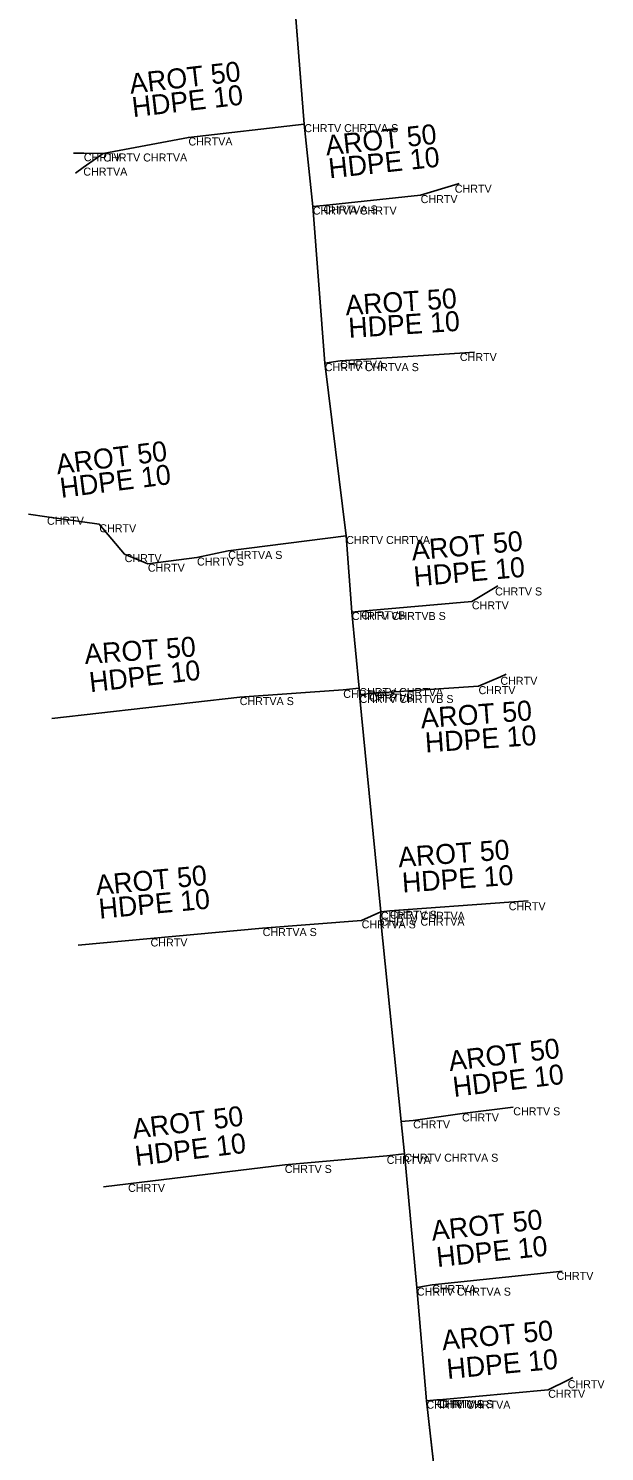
# Model space of a CAD drawing. Extents: x -651943 to -618711, y -1138561 to -1100552.
# Drawn here: x -641106.3 to -641084.8, y -1114595.2 to -1114541.8 of the extents above; entities that cross this region are included whole.
import ezdxf

# ---------------------------------------------------------------- set-up
doc = ezdxf.new("R2010")
doc.units = 0
for name, color, linetype in [('KT optika', 7, 'Continuous'), ('KT trasa', 7, 'Continuous'), ('KT zařízení', 7, 'Continuous')]:
    doc.layers.add(name, color=color, linetype=linetype)

msp = doc.modelspace()

# ---------------------------------------------------------------- linework, layer by layer
at = {"layer": 'KT optika'}
for p, q in [((-641096.85, -1114534.63), (-641096, -1114545.43)), ((-641100.34, -1114545.93), (-641103.53, -1114546.53)), ((-641096, -1114545.43), (-641100.34, -1114545.93)), ((-641096, -1114545.43), (-641095.68, -1114548.52)), ((-641095.68, -1114548.52), (-641095.28, -1114548.48)), ((-641095.68, -1114548.52), (-641095.23, -1114554.39)), ((-641095.28, -1114548.48), (-641091.64, -1114548.09)), ((-641095.23, -1114554.39), (-641094.66, -1114554.3)), ((-641095.23, -1114554.39), (-641094.43, -1114560.87)), ((-641102.73, -1114561.55), (-641103.68, -1114560.43)), ((-641094.43, -1114560.87), (-641098.85, -1114561.43)), ((-641094.43, -1114560.87), (-641094.22, -1114563.72)), ((-641101.86, -1114561.91), (-641102.73, -1114561.55)), ((-641100.02, -1114561.68), (-641101.86, -1114561.91)), ((-641098.85, -1114561.43), (-641100.02, -1114561.68)), ((-641093.86, -1114563.69), (-641089.72, -1114563.32)), ((-641094.22, -1114563.72), (-641093.86, -1114563.69)), ((-641094.22, -1114563.72), (-641093.94, -1114566.57)), ((-641094.54, -1114566.64), (-641098.42, -1114566.91)), ((-641093.94, -1114566.57), (-641094.54, -1114566.64)), ((-641093.93, -1114566.83), (-641093.94, -1114566.57)), ((-641105.453, -1114567.71), (-641098.42, -1114566.91)), ((-641093.13, -1114574.96), (-641093.93, -1114566.83)), ((-641093.85, -1114575.28), (-641097.56, -1114575.57)), ((-641093.13, -1114574.96), (-641093.85, -1114575.28)), ((-641093.13, -1114574.96), (-641093.14, -1114575.18)), ((-641092.79, -1114574.92), (-641093.13, -1114574.96)), ((-641091.92, -1114582.78), (-641090.09, -1114582.52)), ((-641090.09, -1114582.52), (-641088.17, -1114582.29)), ((-641092.371, -1114582.825), (-641091.92, -1114582.78)), ((-641092.91, -1114584.11), (-641096.73, -1114584.45)), ((-641092.25, -1114584.03), (-641092.91, -1114584.11)), ((-641092.25, -1114584.03), (-641091.78, -1114589.05)), ((-641091.78, -1114589.05), (-641091.21, -1114588.95)), ((-641091.78, -1114589.05), (-641091.42, -1114593.29)), ((-641090.95, -1114593.26), (-641086.86, -1114592.88)), ((-641091.42, -1114593.29), (-641090.33, -1114602.87))]:
    msp.add_line(p, q, dxfattribs=at)
for points in [[(-641103.53, -1114546.53), (-641104.26, -1114546.52), (-641104.649, -1114546.515)], [(-641103.53, -1114546.53), (-641104.28, -1114547.06), (-641104.573, -1114547.267)], [(-641091.64, -1114548.09), (-641090.36, -1114547.7), (-641090.194, -1114547.649)], [(-641094.66, -1114554.3), (-641090.17, -1114554.01), (-641089.623, -1114553.975)], [(-641103.68, -1114560.43), (-641105.64, -1114560.15), (-641106.334, -1114560.051)], [(-641089.72, -1114563.32), (-641088.85, -1114562.8), (-641088.748, -1114562.739)], [(-641088.431, -1114566.056), (-641088.65, -1114566.15), (-641089.47, -1114566.5)], [(-641089.47, -1114566.5), (-641093.56, -1114566.78), (-641093.93, -1114566.83)], [(-641087.614, -1114574.548), (-641088.34, -1114574.6), (-641092.79, -1114574.92)], [(-641093.14, -1114575.18), (-641092.371, -1114582.825), (-641092.25, -1114584.03)], [(-641097.56, -1114575.57), (-641101.76, -1114575.96), (-641104.477, -1114576.212)], [(-641096.73, -1114584.45), (-641102.6, -1114585.16), (-641103.517, -1114585.271)], [(-641091.21, -1114588.95), (-641086.55, -1114588.46), (-641086.337, -1114588.438)], [(-641086.86, -1114592.88), (-641086.13, -1114592.52), (-641085.934, -1114592.423)], [(-641091.42, -1114593.29), (-641091.03, -1114593.26), (-641090.95, -1114593.26)]]:
    msp.add_lwpolyline(points, dxfattribs=at)
at = {"layer": 'KT trasa'}
for p, q in [((-641096.85, -1114534.63), (-641096, -1114545.43)), ((-641100.34, -1114545.93), (-641103.53, -1114546.53)), ((-641096, -1114545.43), (-641100.34, -1114545.93)), ((-641096, -1114545.43), (-641095.68, -1114548.52)), ((-641095.68, -1114548.52), (-641095.28, -1114548.48)), ((-641095.68, -1114548.52), (-641095.23, -1114554.39)), ((-641095.28, -1114548.48), (-641091.64, -1114548.09)), ((-641095.23, -1114554.39), (-641094.66, -1114554.3)), ((-641095.23, -1114554.39), (-641094.43, -1114560.87)), ((-641102.73, -1114561.55), (-641103.68, -1114560.43)), ((-641094.43, -1114560.87), (-641098.85, -1114561.43)), ((-641094.43, -1114560.87), (-641094.22, -1114563.72)), ((-641101.86, -1114561.91), (-641102.73, -1114561.55)), ((-641100.02, -1114561.68), (-641101.86, -1114561.91)), ((-641098.85, -1114561.43), (-641100.02, -1114561.68)), ((-641093.86, -1114563.69), (-641089.72, -1114563.32)), ((-641094.22, -1114563.72), (-641093.86, -1114563.69)), ((-641094.22, -1114563.72), (-641093.94, -1114566.57)), ((-641094.54, -1114566.64), (-641098.42, -1114566.91)), ((-641093.94, -1114566.57), (-641094.54, -1114566.64)), ((-641093.93, -1114566.83), (-641093.94, -1114566.57)), ((-641105.453, -1114567.71), (-641098.42, -1114566.91)), ((-641093.13, -1114574.96), (-641093.93, -1114566.83)), ((-641093.85, -1114575.28), (-641097.56, -1114575.57)), ((-641093.13, -1114574.96), (-641093.85, -1114575.28)), ((-641093.13, -1114574.96), (-641093.14, -1114575.18)), ((-641092.79, -1114574.92), (-641093.13, -1114574.96)), ((-641091.92, -1114582.78), (-641090.09, -1114582.52)), ((-641090.09, -1114582.52), (-641088.17, -1114582.29)), ((-641092.371, -1114582.825), (-641091.92, -1114582.78)), ((-641092.91, -1114584.11), (-641096.73, -1114584.45)), ((-641092.25, -1114584.03), (-641092.91, -1114584.11)), ((-641092.25, -1114584.03), (-641091.78, -1114589.05)), ((-641091.78, -1114589.05), (-641091.21, -1114588.95)), ((-641091.78, -1114589.05), (-641091.42, -1114593.29)), ((-641090.95, -1114593.26), (-641086.86, -1114592.88)), ((-641091.42, -1114593.29), (-641090.33, -1114602.87))]:
    msp.add_line(p, q, dxfattribs=at)
for points in [[(-641103.53, -1114546.53), (-641104.26, -1114546.52), (-641104.649, -1114546.515)], [(-641103.53, -1114546.53), (-641104.28, -1114547.06), (-641104.573, -1114547.267)], [(-641091.64, -1114548.09), (-641090.36, -1114547.7), (-641090.194, -1114547.649)], [(-641094.66, -1114554.3), (-641090.17, -1114554.01), (-641089.623, -1114553.975)], [(-641103.68, -1114560.43), (-641105.64, -1114560.15), (-641106.334, -1114560.051)], [(-641089.72, -1114563.32), (-641088.85, -1114562.8), (-641088.748, -1114562.739)], [(-641088.431, -1114566.056), (-641088.65, -1114566.15), (-641089.47, -1114566.5)], [(-641089.47, -1114566.5), (-641093.56, -1114566.78), (-641093.93, -1114566.83)], [(-641087.614, -1114574.548), (-641088.34, -1114574.6), (-641092.79, -1114574.92)], [(-641093.14, -1114575.18), (-641092.371, -1114582.825), (-641092.25, -1114584.03)], [(-641097.56, -1114575.57), (-641101.76, -1114575.96), (-641104.477, -1114576.212)], [(-641096.73, -1114584.45), (-641102.6, -1114585.16), (-641103.517, -1114585.271)], [(-641091.21, -1114588.95), (-641086.55, -1114588.46), (-641086.337, -1114588.438)], [(-641086.86, -1114592.88), (-641086.13, -1114592.52), (-641085.934, -1114592.423)], [(-641091.42, -1114593.29), (-641091.03, -1114593.26), (-641090.95, -1114593.26)]]:
    msp.add_lwpolyline(points, dxfattribs=at)
at = {"layer": 'KT zařízení'}
for p, q in [((-641098.42, -1114566.91), (-641105.453, -1114567.71)), ((-641092.91, -1114584.11), (-641096.73, -1114584.45)), ((-641092.25, -1114584.03), (-641092.91, -1114584.11)), ((-641096.73, -1114584.45), (-641102.6, -1114585.16)), ((-641102.6, -1114585.16), (-641103.517, -1114585.271))]:
    msp.add_line(p, q, dxfattribs=at)
for points in [[(-641096.85, -1114534.63), (-641096, -1114545.43), (-641095.68, -1114548.52), (-641095.23, -1114554.39), (-641094.43, -1114560.87), (-641094.22, -1114563.72), (-641093.94, -1114566.57), (-641093.93, -1114566.83), (-641093.13, -1114574.96), (-641093.14, -1114575.18), (-641092.371, -1114582.825), (-641092.25, -1114584.03), (-641091.78, -1114589.05), (-641091.42, -1114593.29), (-641090.33, -1114602.87)], [(-641096, -1114545.43), (-641100.34, -1114545.93), (-641103.53, -1114546.53), (-641104.26, -1114546.52), (-641104.649, -1114546.515)], [(-641104.573, -1114547.267), (-641104.28, -1114547.06), (-641103.53, -1114546.53)], [(-641090.194, -1114547.649), (-641090.36, -1114547.7), (-641091.64, -1114548.09), (-641095.28, -1114548.48)], [(-641089.623, -1114553.975), (-641090.17, -1114554.01), (-641094.66, -1114554.3), (-641095.23, -1114554.39)], [(-641094.43, -1114560.87), (-641098.85, -1114561.43), (-641100.02, -1114561.68), (-641101.86, -1114561.91), (-641102.73, -1114561.55), (-641103.68, -1114560.43), (-641105.64, -1114560.15), (-641106.334, -1114560.051)], [(-641088.748, -1114562.739), (-641088.85, -1114562.8), (-641089.72, -1114563.32), (-641093.86, -1114563.69)], [(-641088.431, -1114566.056), (-641088.65, -1114566.15), (-641089.47, -1114566.5), (-641093.56, -1114566.78)], [(-641093.94, -1114566.57), (-641094.54, -1114566.64), (-641098.42, -1114566.91)], [(-641092.79, -1114574.92), (-641088.34, -1114574.6), (-641087.614, -1114574.548)], [(-641104.477, -1114576.212), (-641101.76, -1114575.96), (-641097.56, -1114575.57), (-641093.85, -1114575.28), (-641093.13, -1114574.96)], [(-641091.92, -1114582.78), (-641090.09, -1114582.52), (-641088.17, -1114582.29)], [(-641086.337, -1114588.438), (-641086.55, -1114588.46), (-641091.21, -1114588.95), (-641091.78, -1114589.05)], [(-641091.03, -1114593.26), (-641090.95, -1114593.26), (-641086.86, -1114592.88), (-641086.13, -1114592.52), (-641085.934, -1114592.423)]]:
    msp.add_lwpolyline(points, dxfattribs=at)

# ---------------------------------------------------------------- texts
for s, rotation, p in [('AROT 50', 6.5719, (-641102.508, -1114544.291)), ('HDPE 10', 6.5719, (-641102.413, -1114545.171)), ('AROT 50', 6.1155, (-641095.168, -1114546.607)), ('HDPE 10', 6.1155, (-641095.053, -1114547.464)), ('AROT 50', 3.6955, (-641094.438, -1114552.595)), ('HDPE 10', 3.6955, (-641094.324, -1114553.446)), ('AROT 50', 7.125, (-641105.253, -1114558.559)), ('HDPE 10', 7.2207, (-641105.108, -1114559.444)), ('AROT 50', 5.1071, (-641091.952, -1114561.79)), ('HDPE 10', 5.1071, (-641091.869, -1114562.767)), ('AROT 50', 3.9807, (-641104.214, -1114565.673)), ('HDPE 10', 6.4895, (-641104.015, -1114566.729)), ('AROT 50', 4.2317, (-641091.615, -1114568.083)), ('HDPE 10', 3.9163, (-641091.452, -1114568.989)), ('AROT 50', 4.1131, (-641092.458, -1114573.291)), ('AROT 50', 5.3051, (-641103.786, -1114574.338)), ('HDPE 10', 4.1131, (-641092.311, -1114574.243)), ('HDPE 10', 5.299, (-641103.668, -1114575.221)), ('AROT 50', 6.831, (-641090.546, -1114580.931)), ('HDPE 10', 6.831, (-641090.39, -1114581.902)), ('AROT 50', 6.8967, (-641102.399, -1114583.473)), ('HDPE 10', 6.8967, (-641102.3, -1114584.492)), ('AROT 50', 6.0026, (-641091.203, -1114587.29)), ('HDPE 10', 6.0026, (-641091.012, -1114588.282)), ('AROT 50', 5.3081, (-641090.813, -1114591.399)), ('HDPE 10', 5.3081, (-641090.632, -1114592.475))]:
    msp.add_text(s, height=0.75, rotation=rotation, dxfattribs=at).set_placement(p)
for s, p in [('CHRTVA', (-641100.34, -1114546.23)), ('CHRTV CHRTVA S', (-641096, -1114545.73)), ('CHRTV', (-641104.26, -1114546.82)), ('CHRTV CHRTVA', (-641103.53, -1114546.83)), ('CHRTVA', (-641104.28, -1114547.36)), ('CHRTV', (-641090.36, -1114548)), ('CHRTVA CHRTV', (-641095.68, -1114548.82)), ('CHRTVA S', (-641095.28, -1114548.78)), ('CHRTV', (-641091.64, -1114548.39)), ('CHRTV CHRTVA S', (-641095.23, -1114554.69)), ('CHRTVA', (-641094.66, -1114554.6)), ('CHRTV', (-641090.17, -1114554.31)), ('CHRTV', (-641105.64, -1114560.45)), ('CHRTV', (-641103.68, -1114560.73)), ('CHRTV CHRTVA', (-641094.43, -1114561.17)), ('CHRTV', (-641102.73, -1114561.85)), ('CHRTV', (-641101.86, -1114562.21)), ('CHRTV S', (-641100.02, -1114561.98)), ('CHRTVA S', (-641098.85, -1114561.73)), ('CHRTV S', (-641088.85, -1114563.1)), ('CHRTV', (-641089.72, -1114563.62)), ('CHRTV CHRTVB S', (-641094.22, -1114564.02)), ('CHRTVB', (-641093.86, -1114563.99)), ('CHRTV', (-641088.65, -1114566.45)), ('CHRTVA S', (-641094.54, -1114566.94)), ('CHRTV CHRTVA', (-641093.94, -1114566.87)), ('CHRTV', (-641089.47, -1114566.8)), ('CHRTVA S', (-641098.42, -1114567.21)), ('CHRTV CHRTVB S', (-641093.93, -1114567.13)), ('CHRTVB', (-641093.56, -1114567.08)), ('CHRTV', (-641088.34, -1114574.9)), ('CHRTVA S', (-641093.85, -1114575.58)), ('CHRTV CHRTVA', (-641093.14, -1114575.48)), ('CHRTV CHRTVA', (-641093.13, -1114575.26)), ('CHRTV S', (-641092.79, -1114575.22)), ('CHRTVA S', (-641097.56, -1114575.87)), ('CHRTV', (-641101.76, -1114576.26)), ('CHRTV', (-641090.09, -1114582.82)), ('CHRTV S', (-641088.17, -1114582.59)), ('CHRTV', (-641091.92, -1114583.08)), ('CHRTVA', (-641092.91, -1114584.41)), ('CHRTV CHRTVA S', (-641092.25, -1114584.33)), ('CHRTV S', (-641096.73, -1114584.75)), ('CHRTV', (-641102.6, -1114585.46)), ('CHRTV', (-641086.55, -1114588.76)), ('CHRTV CHRTVA S', (-641091.78, -1114589.35)), ('CHRTVA', (-641091.21, -1114589.25)), ('CHRTV', (-641086.86, -1114593.18)), ('CHRTV', (-641086.13, -1114592.82)), ('CHRTV CHRTVA', (-641091.42, -1114593.59)), ('CHRTV S', (-641091.03, -1114593.56)), ('CHRTVA S', (-641090.95, -1114593.56))]:
    msp.add_text(s, height=0.3, dxfattribs=at).set_placement(p)

doc.saveas('drawing.dxf')
